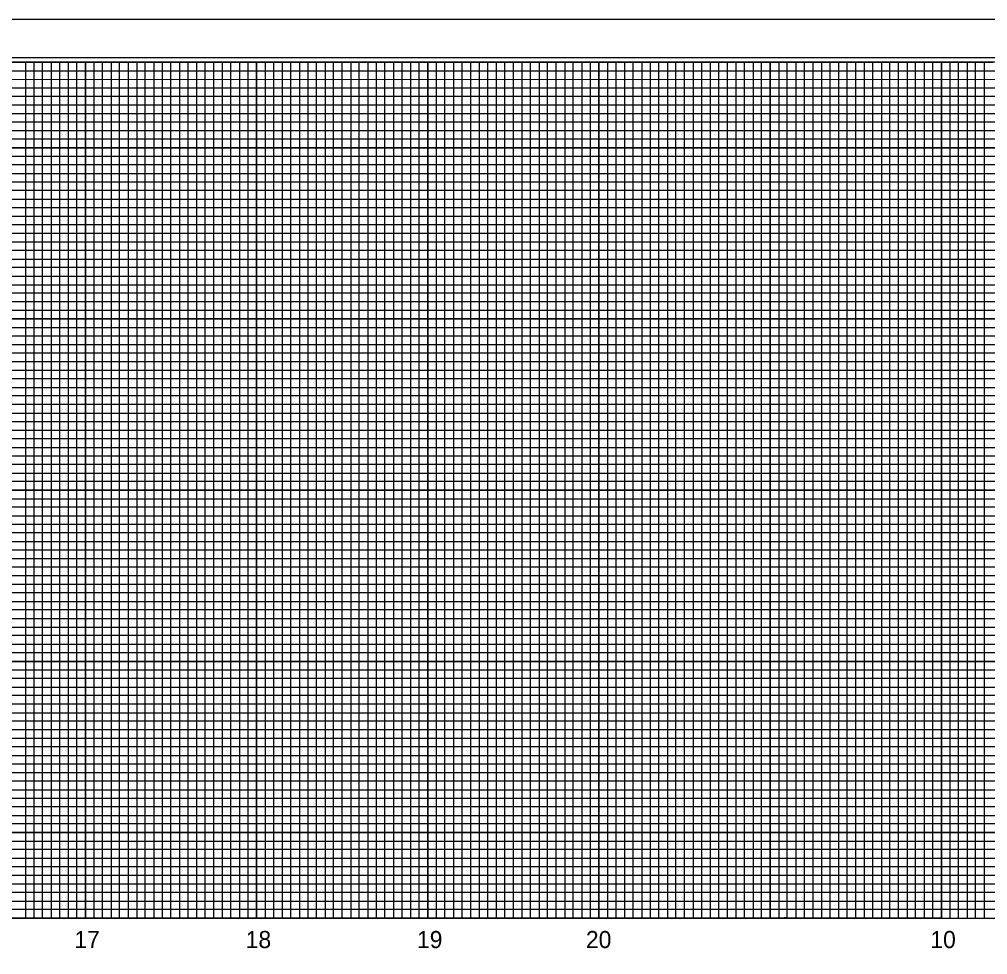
# Model space of a CAD drawing. Extents: x 2186391 to 2188300, y 74582 to 75682.
# Drawn here: x 2186969 to 2187535, y 75136 to 75682 of the extents above; entities that cross this region are included whole.
import ezdxf

# ---------------------------------------------------------------- set-up
doc = ezdxf.new("R2010")
doc.units = 0
for name, color, linetype in [('Exist Structure Minor Culvert Topo', 7, 'Continuous'), ('Old_Level_1', 7, 'Continuous'), ('Old_Level_11', 7, 'Continuous'), ('Old_Level_2', 7, 'Continuous'), ('Scratch_Level_0', 7, 'Continuous'), ('Sheet Cutting Line CELL', 7, 'Continuous'), ('Sheet Plot Border Inside CELL', 7, 'Continuous'), ('Sheet Plot Border Outside CELL', 7, 'Continuous'), ('Sheet Sticker Exception Certification CELL', 7, 'Continuous'), ('Sheet Sticker Incomplete CELL', 7, 'Continuous'), ('Sheet Sticker Preliminary CELL', 7, 'Continuous')]:
    doc.layers.add(name, color=color, linetype=linetype)

msp = doc.modelspace()

# ---------------------------------------------------------------- linework, layer by layer
at = {"layer": 'Exist Structure Minor Culvert Topo'}
msp.add_lwpolyline([(2186607.69, 75657.28), (2187507.69, 75657.28), (2187507.69, 75157.28), (2186607.69, 75157.28)], close=True, dxfattribs=at)
at = {"layer": 'Old_Level_11'}
for p, q in [((2187007.69, 75157.28), (2187007.69, 75657.28)), ((2187057.69, 75157.28), (2187057.69, 75657.28)), ((2187107.69, 75157.28), (2187107.69, 75657.28)), ((2187157.69, 75157.28), (2187157.69, 75657.28)), ((2187207.69, 75157.28), (2187207.69, 75657.28)), ((2187257.69, 75157.28), (2187257.69, 75657.28)), ((2187307.69, 75157.28), (2187307.69, 75657.28)), ((2187357.69, 75157.28), (2187357.69, 75657.28)), ((2187407.69, 75157.28), (2187407.69, 75657.28)), ((2187457.69, 75157.28), (2187457.69, 75657.28)), ((2187507.69, 75157.28), (2187507.69, 75657.28)), ((2187857.64, 75607.28), (2186557.69, 75607.28)), ((2187857.64, 75557.28), (2186557.69, 75557.28)), ((2187857.69, 75507.28), (2186557.69, 75507.28)), ((2188057.69, 75457.28), (2186557.69, 75457.28)), ((2188057.69, 75407.28), (2186557.69, 75407.28)), ((2188057.69, 75357.28), (2186557.69, 75357.28)), ((2188057.69, 75307.28), (2186557.69, 75307.28)), ((2188057.69, 75257.28), (2186557.69, 75257.28)), ((2188057.69, 75207.28), (2186557.69, 75207.28))]:
    msp.add_line(p, q, dxfattribs=at)
at = {"layer": 'Old_Level_2'}
msp.add_line((2186557.69, 75632.28), (2187857.64, 75632.28), dxfattribs=at)
for points in [[(2186932.69, 75157.28), (2186982.69, 75157.28), (2186982.69, 75657.28), (2187032.69, 75657.28), (2187032.69, 75157.28), (2187082.69, 75157.28), (2187082.69, 75657.28), (2187132.69, 75657.28), (2187132.69, 75157.28), (2187182.69, 75157.28), (2187182.69, 75157.28), (2187182.69, 75657.28), (2187232.69, 75657.28), (2187232.69, 75157.28), (2187282.69, 75157.28), (2187282.69, 75657.28), (2187332.69, 75657.28), (2187332.69, 75157.28), (2187382.69, 75157.28), (2187382.69, 75657.28), (2187432.69, 75657.28), (2187432.69, 75157.28), (2187482.69, 75157.28), (2187482.69, 75657.28), (2187532.69, 75657.28), (2187532.69, 75157.28), (2187582.69, 75157.28)], [(2187857.69, 75582.28), (2186557.69, 75582.28), (2186557.69, 75532.28), (2187857.69, 75532.28)], [(2188057.69, 75482.28), (2186557.69, 75482.28), (2186557.69, 75432.28), (2187882.69, 75432.28)], [(2188057.69, 75382.28), (2186557.69, 75382.28), (2186557.69, 75332.28), (2188057.69, 75332.28)], [(2188057.69, 75282.28), (2186557.69, 75282.28), (2186557.69, 75232.28), (2188057.69, 75232.28)], [(2188057.69, 75182.28), (2186557.69, 75182.28)]]:
    msp.add_lwpolyline(points, dxfattribs=at)
at = {"layer": 'Scratch_Level_0'}
msp.add_line((2188074.69, 75682.28), (2186390.69, 75682.28), dxfattribs=at)
at = {"layer": 'Sheet Cutting Line CELL'}
msp.add_line((2186557.69, 75157.28), (2188057.69, 75157.28), dxfattribs=at)
msp.add_lwpolyline([(2188057.69, 75657.28), (2186557.69, 75657.28), (2186557.69, 74607.28), (2188057.69, 74607.28)], close=True, dxfattribs=at)
at = {"layer": 'Sheet Plot Border Inside CELL'}
msp.add_lwpolyline([(2186607.69, 75496.23), (2186607.69, 75157.28), (2188007.69, 75157.28), (2188007.69, 75496.23)], dxfattribs=at)
at = {"layer": 'Sheet Plot Border Outside CELL'}
for p, q in [((2186607.69, 75652.28), (2187857.69, 75652.28)), ((2187857.69, 75647.28), (2186607.69, 75646.93)), ((2186607.69, 75642.28), (2187857.69, 75642.28)), ((2187857.64, 75522.28), (2186607.69, 75522.28)), ((2187857.69, 75517.28), (2186607.69, 75517.28)), ((2187857.69, 75512.28), (2186607.69, 75512.28)), ((2186607.69, 75502.28), (2187857.69, 75502.28)), ((2187857.69, 75497.28), (2186607.69, 75497.28)), ((2186607.69, 75492.28), (2188007.69, 75492.28)), ((2188007.69, 75472.28), (2186607.69, 75472.28)), ((2186607.69, 75467.28), (2188007.69, 75467.28)), ((2188007.69, 75447.28), (2186607.69, 75447.28)), ((2186607.69, 75442.28), (2188007.69, 75442.28)), ((2188007.69, 75422.28), (2186607.69, 75422.28)), ((2186607.69, 75417.28), (2188007.69, 75417.28)), ((2188007.69, 75412.28), (2186607.69, 75412.28)), ((2186607.69, 75402.28), (2188007.69, 75402.28)), ((2188007.69, 75397.28), (2186607.69, 75397.28)), ((2186607.69, 75392.28), (2188007.69, 75392.28)), ((2188007.69, 75387.28), (2186607.69, 75387.28)), ((2186607.69, 75377.28), (2188007.69, 75377.28)), ((2188007.69, 75372.28), (2186607.69, 75372.28)), ((2186607.69, 75367.28), (2188007.69, 75367.28)), ((2188007.69, 75362.28), (2186607.69, 75362.28)), ((2186607.69, 75352.28), (2188007.69, 75352.28)), ((2188007.69, 75347.28), (2186607.69, 75347.28)), ((2186607.69, 75342.28), (2188007.69, 75342.28)), ((2188007.69, 75337.28), (2186607.69, 75337.28)), ((2186607.69, 75327.28), (2188007.69, 75327.28)), ((2188007.69, 75322.28), (2186607.69, 75322.28)), ((2186607.69, 75317.28), (2188007.69, 75317.28)), ((2188007.69, 75312.28), (2186607.69, 75312.28)), ((2186607.69, 75302.28), (2188007.69, 75302.28)), ((2188007.69, 75297.28), (2186607.69, 75297.28)), ((2186607.69, 75292.28), (2188007.69, 75292.28)), ((2188007.69, 75287.28), (2186607.69, 75287.28)), ((2186607.69, 75277.28), (2188007.69, 75277.28)), ((2188007.69, 75272.28), (2186607.69, 75272.28)), ((2188007.69, 75267.28), (2186607.69, 75267.28)), ((2188007.69, 75262.28), (2186607.69, 75262.28)), ((2186607.69, 75252.28), (2188007.69, 75252.28)), ((2188007.69, 75247.28), (2186607.69, 75247.28)), ((2186607.69, 75242.28), (2188007.69, 75242.28)), ((2188007.69, 75237.28), (2186607.69, 75237.28)), ((2186607.69, 75227.28), (2188007.69, 75227.28)), ((2188007.69, 75222.28), (2186607.69, 75222.28)), ((2186607.69, 75217.28), (2188007.69, 75217.28)), ((2188007.69, 75212.28), (2186607.69, 75212.28)), ((2186607.69, 75202.28), (2188007.69, 75202.28)), ((2188007.69, 75197.28), (2186607.69, 75197.28)), ((2186607.69, 75192.28), (2188007.69, 75192.28)), ((2188007.69, 75187.28), (2186607.69, 75187.28)), ((2186607.69, 75177.28), (2188007.69, 75177.28)), ((2188007.69, 75172.28), (2186607.69, 75172.28)), ((2186607.69, 75167.28), (2188007.69, 75167.28))]:
    msp.add_line(p, q, dxfattribs=at)
for points in [[(2186967.69, 75657.28), (2186972.69, 75657.28), (2186972.69, 75157.28), (2186977.69, 75157.28), (2186977.69, 75657.28), (2186987.69, 75657.28), (2186987.69, 75157.28), (2186992.69, 75157.28), (2186992.69, 75657.28), (2186997.69, 75657.28), (2186997.69, 75157.28), (2187002.69, 75157.28), (2187002.69, 75657.28), (2187012.69, 75657.28), (2187012.69, 75157.28), (2187017.69, 75157.28), (2187017.69, 75657.28), (2187022.69, 75657.28), (2187022.69, 75157.28), (2187027.69, 75157.28), (2187027.69, 75657.28), (2187037.69, 75657.28), (2187037.69, 75157.28), (2187042.69, 75157.28), (2187042.69, 75657.28), (2187047.69, 75657.28), (2187047.69, 75157.28), (2187052.69, 75157.28), (2187052.69, 75657.28), (2187062.69, 75657.28), (2187062.69, 75157.28), (2187067.69, 75157.28), (2187067.69, 75657.28), (2187072.69, 75657.28), (2187072.69, 75157.28), (2187077.69, 75157.28), (2187077.69, 75657.28), (2187087.69, 75657.28), (2187087.69, 75157.28), (2187092.69, 75157.28), (2187092.69, 75657.28), (2187097.69, 75657.28), (2187097.69, 75157.28), (2187102.69, 75157.28), (2187102.69, 75657.28), (2187112.69, 75657.28), (2187112.69, 75157.28), (2187117.69, 75157.28), (2187117.69, 75657.28), (2187122.69, 75657.28), (2187122.69, 75157.28), (2187127.69, 75157.28), (2187127.69, 75657.28), (2187137.69, 75657.28)], [(2187137.69, 75657.28), (2187137.69, 75157.28), (2187142.69, 75157.28), (2187142.69, 75657.28), (2187147.69, 75657.28), (2187147.69, 75157.28), (2187152.69, 75157.28), (2187152.69, 75657.28), (2187162.69, 75657.28), (2187162.69, 75157.28), (2187167.69, 75157.28), (2187167.69, 75657.28), (2187172.69, 75657.28), (2187172.69, 75157.28), (2187177.69, 75157.28), (2187177.69, 75657.28), (2187187.69, 75657.28), (2187187.69, 75157.28), (2187192.69, 75157.28), (2187192.69, 75657.28), (2187197.69, 75657.28), (2187197.69, 75157.28), (2187202.69, 75157.28), (2187202.69, 75657.28), (2187212.69, 75657.28), (2187212.69, 75157.28), (2187217.69, 75157.28), (2187217.69, 75657.28), (2187222.69, 75657.28), (2187222.69, 75157.28), (2187227.69, 75157.28), (2187227.69, 75657.28), (2187237.69, 75657.28), (2187237.69, 75157.28), (2187242.69, 75157.28), (2187242.69, 75657.28), (2187247.69, 75657.28), (2187247.69, 75157.28), (2187252.69, 75157.28), (2187252.69, 75657.28), (2187262.69, 75657.28), (2187262.69, 75157.28), (2187262.69, 75157.28), (2187267.69, 75157.28), (2187267.69, 75657.28), (2187272.69, 75657.28), (2187272.69, 75157.28), (2187277.69, 75157.28), (2187277.69, 75657.28), (2187287.69, 75657.28), (2187287.69, 75157.28), (2187292.69, 75157.28), (2187292.69, 75657.28), (2187297.69, 75657.28), (2187297.69, 75157.28), (2187302.69, 75157.28), (2187302.69, 75657.28), (2187312.69, 75657.28), (2187312.69, 75157.28), (2187317.69, 75157.28), (2187317.69, 75657.28), (2187322.69, 75657.28), (2187322.69, 75157.28), (2187327.69, 75157.28), (2187327.69, 75657.28), (2187337.69, 75657.28), (2187337.69, 75157.28), (2187342.69, 75157.28), (2187342.69, 75657.28), (2187347.69, 75657.28), (2187347.69, 75157.28), (2187352.69, 75157.28), (2187352.69, 75657.28), (2187362.69, 75657.28), (2187362.69, 75157.28), (2187367.69, 75157.28), (2187367.69, 75657.28), (2187372.69, 75657.28), (2187372.69, 75157.28), (2187377.69, 75157.28), (2187377.69, 75657.28), (2187387.69, 75657.28), (2187387.69, 75157.28), (2187392.69, 75157.28), (2187392.69, 75657.28), (2187397.69, 75657.28), (2187397.69, 75157.28), (2187402.69, 75157.28), (2187402.69, 75657.28), (2187412.69, 75657.28), (2187412.69, 75157.28), (2187417.39, 75157.83), (2187417.69, 75157.28), (2187417.69, 75657.28), (2187422.69, 75657.28), (2187422.69, 75157.28), (2187427.69, 75157.28), (2187427.69, 75657.28), (2187437.69, 75657.28), (2187437.69, 75157.28), (2187442.69, 75157.28)], [(2187442.69, 75157.28), (2187442.69, 75657.28), (2187447.69, 75657.28), (2187447.69, 75157.28), (2187452.69, 75157.28), (2187452.69, 75657.28), (2187462.69, 75657.28), (2187462.69, 75157.28), (2187467.69, 75157.28), (2187467.69, 75657.28), (2187472.69, 75657.28), (2187472.69, 75157.28), (2187477.69, 75157.28), (2187477.69, 75657.28), (2187487.69, 75657.28), (2187487.69, 75157.28), (2187492.69, 75157.28), (2187492.69, 75657.28), (2187497.69, 75657.28), (2187497.69, 75157.28), (2187502.69, 75157.28), (2187502.69, 75657.28), (2187512.69, 75657.28), (2187512.69, 75157.28), (2187517.69, 75157.28), (2187517.69, 75657.28), (2187522.69, 75657.28), (2187522.69, 75157.28), (2187527.69, 75157.28), (2187527.69, 75657.28), (2187537.69, 75657.28)], [(2187857.69, 75637.28), (2186607.69, 75637.28), (2186607.69, 75627.28), (2187857.69, 75627.28)], [(2187857.64, 75622.28), (2186607.69, 75622.28), (2186607.69, 75617.28), (2187857.69, 75617.28)], [(2187857.69, 75612.28), (2186607.69, 75612.28), (2186607.69, 75602.28), (2187857.69, 75602.28)], [(2187857.69, 75597.28), (2186607.69, 75597.28), (2186607.69, 75592.28), (2187857.69, 75592.28)], [(2187857.69, 75587.28), (2186607.69, 75587.28), (2186607.69, 75577.28), (2187857.69, 75577.28)], [(2187857.69, 75572.28), (2186607.69, 75572.28), (2186607.69, 75567.28), (2187857.69, 75567.28)], [(2187857.69, 75562.28), (2186607.69, 75562.28), (2186607.69, 75552.28), (2187857.69, 75552.28)], [(2187857.69, 75547.18), (2186607.79, 75547.18), (2186607.79, 75542.28), (2187857.69, 75542.28)], [(2187857.69, 75537.28), (2186607.69, 75537.28), (2186607.69, 75527.28), (2187857.69, 75527.28)], [(2188007.69, 75487.28), (2186607.69, 75487.28), (2186607.69, 75477.28), (2188007.69, 75477.28)], [(2188007.69, 75462.28), (2186607.69, 75462.28), (2186607.69, 75452.28), (2188007.69, 75452.28)], [(2188007.69, 75437.28), (2186607.69, 75437.28), (2186607.69, 75427.28), (2188007.69, 75427.28)], [(2188007.69, 75162.28), (2186607.69, 75162.28)]]:
    msp.add_lwpolyline(points, dxfattribs=at)
at = {"layer": 'Sheet Sticker Exception Certification CELL'}
for points in [[(2186957.69, 75657.28), (2187007.69, 75657.28), (2187007.69, 75157.28), (2187057.69, 75157.28), (2187057.69, 75657.28), (2187107.69, 75657.28), (2187107.69, 75157.28), (2187157.69, 75157.28), (2187157.69, 75657.28), (2187207.69, 75657.28), (2187207.69, 75157.28), (2187257.69, 75157.28), (2187257.69, 75657.28), (2187307.69, 75657.28), (2187307.69, 75157.28), (2187357.69, 75157.28), (2187357.69, 75657.28), (2187407.69, 75657.28), (2187407.69, 75157.28), (2187457.69, 75157.28), (2187457.69, 75657.28), (2187507.69, 75657.28), (2187507.69, 75157.28), (2187557.69, 75157.28)], [(2186557.69, 75607.28), (2187857.69, 75607.28)], [(2187857.69, 75557.28), (2186557.69, 75557.28), (2186557.69, 75507.28), (2187857.69, 75507.28)], [(2188057.69, 75457.28), (2186557.69, 75457.28), (2186557.69, 75407.28), (2188057.69, 75407.28)], [(2188057.69, 75357.28), (2186557.69, 75357.28), (2186557.69, 75307.28), (2188057.69, 75307.28)], [(2188057.69, 75257.28), (2186557.69, 75257.28), (2186557.69, 75257.28), (2186557.69, 75207.28), (2188057.69, 75207.28)]]:
    msp.add_lwpolyline(points, dxfattribs=at)
at = {"layer": 'Sheet Sticker Incomplete CELL'}
msp.add_lwpolyline([(2186390.69, 74582.28), (2188074.69, 74582.28), (2188074.69, 75682.28), (2186390.69, 75682.28)], close=True, dxfattribs=at)
at = {"layer": 'Sheet Sticker Preliminary CELL'}
msp.add_lwpolyline([(2186403.69, 74604.73), (2188070.19, 74604.73), (2188070.19, 75659.83), (2186403.69, 75659.83)], close=True, dxfattribs=at)

# ---------------------------------------------------------------- texts
at = {"layer": 'Old_Level_1'}
for s, p in [('17', (2187001.23, 75139.78)), ('18', (2187101.35, 75139.78)), ('19', (2187201.4, 75139.78)), ('20', (2187300.08, 75139.78)), ('10', (2187501.27, 75139.78))]:
    msp.add_text(s, height=10, dxfattribs=at).set_placement(p)

doc.saveas('drawing.dxf')
